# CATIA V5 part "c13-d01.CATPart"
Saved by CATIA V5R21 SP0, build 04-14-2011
Part number: Part1
Bounding box of the stored display mesh (mm): x -175 to 175, y -250 to 250, z -108 to 0
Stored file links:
  D:\CATIA V5R21 E-RESOURCES\CATIA-V5R21\catia-v5r21-prt\c13-catia-v5r20-prt\c13-catia-v5r20-figr-13-8\cat_v5r21_c13-d01.CATPart
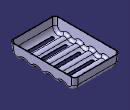
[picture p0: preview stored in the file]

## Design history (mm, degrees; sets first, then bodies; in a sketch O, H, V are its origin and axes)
Set1
  Plane1: type Offset, RefPlane yz-plane, Offset 120
  Plane2: type Offset, RefPlane xy-plane, Offset 108, reversed
Body1 (main body)
  Sketch1 on yz-plane, origin (0, 0, 0), H (0, 1, 0), V (0, 0, 1)
    line L1 (-250, 0) -> (250, 0)
    point P1 (-250, 0)
    point P2 (250, 0)
    line L2 (-250, 0) -> (-250, -100)
    point P3 (-250, -50)
    construction arc A1 centre (-200, -50) radius 50 from (-250, -50) to (-161.5385, -81.9486) ccw
    point P4 (-200, -50)
    construction arc A2 centre (-150, -91.5331) radius 15 from (-161.5385, -81.9486) to (-138.4615, -81.9486) cw
    construction arc A3 centre (-100, -50) radius 50 from (-138.4615, -81.9486) to (-61.5385, -81.9486) ccw
    point P8 (-100, -50)
    construction arc A4 centre (-50, -91.5331) radius 15 from (-61.5385, -81.9486) to (-38.4615, -81.9486) cw
    point P10 (-50, -91.5331)
    construction arc A5 centre (0, -50) radius 50 from (-38.4615, -81.9486) to (38.4615, -81.9486) ccw
    point P12 (0, -50)
    construction arc A6 centre (50, -91.5331) radius 15 from (38.4615, -81.9486) to (61.5385, -81.9486) cw
    point P14 (50, -91.5331)
    construction arc A7 centre (100, -50) radius 50 from (61.5385, -81.9486) to (138.4615, -81.9486) ccw
    point P16 (100, -50)
    construction arc A8 centre (150, -91.5331) radius 15 from (138.4615, -81.9486) to (161.5385, -81.9486) cw
    construction arc A9 centre (200, -50) radius 50 from (161.5385, -81.9486) to (250, -50) ccw
    point P21 (250, -50)
    line L3 (250, -100) -> (250, 0)
    construction line L4 (200, -50) -> (-159.8058, -50)
    construction line L5 (-150, -91.5331) -> (150, -91.5331)
    line L6 (-250, -100) -> (250, -100)
    length L1 = 500
    radius A1 = 50
    radius A3 = 50
    radius A5 = 50
    radius A7 = 50
    radius A9 = 50
    distance P2 V = 250
    radius A2 = 15
    radius A4 = 15
    radius A6 = 15
    radius A8 = 15
    coincidence: P1 H, L4 P4, P16 L4, P12 L4, P8 L4, P10 L5, P14 L5, P3 L2, P21 L3
    horizontal: L1 H, L4 H, L5 H, L6 H
    vertical: L2 V, L3 V
    tangency: A1 L1, A1 L2, A2 A1, A3 A2, A4 A3, A5 A4, A6 A5, A7 A6, A8 A7, A9 A8, L3 A9, L6 A1
  Pad1: profile Sketch1, direction (1, 0, 0), length 175, mirrored extent
  Draft1: Angle -5, Neutral face of Pad1, PullDir face of Pad1, SupportToDraft (face of Pad1; face of Pad1; face of Pad1; face of Pad1)
  Sketch2 on yz-plane, origin (0, 0, 0), H (0, 1, 0), V (0, 0, 1)
    point P1 (-245.2443, -54.3578)
    arc A1 centre (-195.4346, -50) radius 50 from (-245.2443, -54.3578) to (-162.8621, -87.9346) ccw
    arc A2 centre (-146.5759, -106.902) radius 25 from (-162.8621, -87.9346) to (-130.2897, -87.9346) cw
    arc A3 centre (-97.7173, -50) radius 50 from (-130.2897, -87.9346) to (-65.1449, -87.9346) ccw
    point P6 (-97.7173, -50)
    arc A4 centre (-48.8586, -106.902) radius 25 from (-65.1449, -87.9346) to (-32.5724, -87.9346) cw
    point P8 (-48.8586, -106.902)
    arc A5 centre (0, -50) radius 50 from (-32.5724, -87.9346) to (32.5724, -87.9346) ccw
    point P10 (0, -50)
    arc A6 centre (48.8586, -106.902) radius 25 from (32.5724, -87.9346) to (65.1449, -87.9346) cw
    point P12 (48.8586, -106.902)
    arc A7 centre (97.7173, -50) radius 50 from (65.1449, -87.9346) to (130.2897, -87.9346) ccw
    point P14 (97.7173, -50)
    arc A8 centre (146.5759, -106.902) radius 25 from (130.2897, -87.9346) to (162.8621, -87.9346) cw
    arc A9 centre (195.4346, -50) radius 50 from (162.8621, -87.9346) to (245.2443, -54.3578) ccw
    point P19 (245.2443, -54.3578)
    reference projected line E1 (241.2511, -100) -> (250, 0) from edge [face of Pad1 | face of Pad1]
    reference projected line E2 (241.2511, -100) -> (250, 0) from edge [face of Pad1 | face of Pad1]
    reference projected line E3 (-250, 0) -> (-241.2511, -100) from edge [face of Pad1 | face of Pad1]
    reference projected line E4 (-250, 0) -> (-241.2511, -100) from edge [face of Pad1 | face of Pad1]
    reference projected line E5 (241.2511, -100) -> (-241.2511, -100) from edge [face of Pad1 | face of Pad1]
    reference projected line E6 (241.2511, -100) -> (-241.2511, -100) from edge [face of Pad1 | face of Pad1]
    reference projected line E7 (241.2511, -100) -> (-241.2511, -100) from edge [face of Pad1 | face of Pad1]
    reference projected line E8 (241.2511, -100) -> (-241.2511, -100) from edge [face of Pad1 | face of Pad1]
    reference projected line E9 (241.2511, -100) -> (-241.2511, -100) from edge [face of Pad1 | face of Pad1]
    construction line L1 (-195.4346, -50) -> (195.4346, -50)
    axis line L2 (146.5759, -106.902) -> (-146.5759, -106.902)
    radius A1 = 50
    radius A2 = 25
    radius A4 = 25
    radius A6 = 25
    radius A8 = 25
    tangency: A2 A1, A3 A2, A4 A3, A5 A4, A6 A5, A7 A6, A8 A7, A9 A8, A9 E1, A1 E4, A1 E5, A3 E6, A5 E7, A7 E8, A9 E9
    coincidence: P19 E2, P1 E3, P6 L1, P10 L1, P14 L1, P8 L2, L2 P12
    horizontal: L1 H, L2 H
  Pocket1: profile Sketch2, direction (-1, 0, 0), length 175, opposite side through (limit type 3)
  Fillet1: radius 25, on 2 edges
  Shell1: ExtOffset 0, Face face of Pad1, IntOffset 5
  Sketch3 on xy-plane, origin (0, 0, 0), H (1, 0, 0), V (0, 1, 0)
    construction line L1 (-105, -200) -> (105, -200)
    point P2 (105, -200)
    line L2 (-105, -188) -> (105, -188)
    line L3 (105, -212) -> (-105, -212)
    arc A1 centre (105, -200) radius 12 from (105, -188) to (105, -212) cw
    arc A2 centre (-105, -200) radius 12 from (-105, -212) to (-105, -188) cw
    reference projected line E1 (-175, -250) -> (175, -250) from edge [face of Pad1 | face of Pad1]
    reference projected line E2 (175, -250) -> (175, 250) from edge [face of Pad1 | face of Pad1]
    distance L1 E1 = 50
    distance E2 P2 = 70
    radius A1 = 12
    length L1 = 210
    horizontal: L1 H
    tangency: A1 L2, A2 L2, A1 L3, A2 L3
    parallelism: L1 L2
  Pocket2: profile Sketch3, direction (0, 0, -1), through (limit type 3)
  RectPattern1: of Pocket2, direction 1 instances 5, spacing 101, along edge [face of Pad1 | face of Pad1]
  Sketch4 on Plane2, origin (0, 0, -108), H (1, 0, 0), V (0, 1, 0)
    circle A1 centre (130, -200) radius 5
    point P1 (130, -200)
    reference projected line E1 (175, -250) -> (175, 250) from edge [face of Pad1 | face of Pad1]
    reference projected line E2 (-175, -250) -> (175, -250) from edge [face of Pad1 | face of Pad1]
    distance P1 E1 = 45
    distance P1 E2 = 50
    radius A1 = 5
  Pad2: profile Sketch4, direction (0, 0, 1), up to the existing solid (limit type 2)
  Draft2: Angle -5, Neutral face of Pad2, PullDir face of Pad1, SupportToDraft face of Pad2
  Fillet2: radius 2, on edge [face of Pad2 | face of Pad2]
  RectPattern2: of Pad2, Sketch4, Draft2, Fillet2, direction 1 instances 2, spacing 402, along edge [face of Pad1 | face of Pad1], direction 2 instances 2, spacing 260, along edge [face of Pad1 | face of Pad1] reversed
